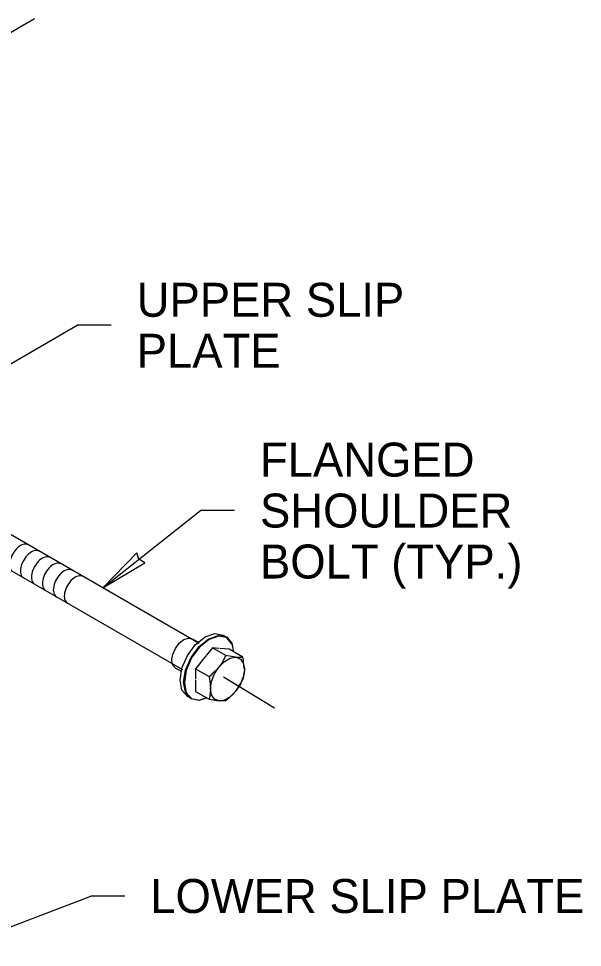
# Model space of a CAD drawing. Extents: x 99862 to 103151, y 99997 to 117076.
# Drawn here: x 101923.2 to 102188.8, y 116043.6 to 116481.1 of the extents above; entities that cross this region are included whole.
import ezdxf

# ---------------------------------------------------------------- set-up
doc = ezdxf.new("R2010")
doc.units = 0
for name, color, linetype in [('Level 13', 7, 'Continuous'), ('Level 15', 7, 'Continuous'), ('Level 20', 7, 'Continuous'), ('Level 3', 7, 'Continuous'), ('Level 5', 7, 'Continuous'), ('Level 9', 7, 'Continuous')]:
    doc.layers.add(name, color=color, linetype=linetype)

msp = doc.modelspace()

# ---------------------------------------------------------------- linework, layer by layer
at = {"layer": 'Level 13'}
for p, q in [((102008.19, 116186.76), (101917.42, 116239.17)), ((102000.5, 116174.38), (101910.13, 116226.55))]:
    msp.add_line(p, q, dxfattribs=at)
for centre, start_param, end_param in [((101924.08, 116226.91), 6.283172, 9.424785), ((101929.23, 116223.93), 6.283179, 9.424784), ((101934.39, 116220.96), 6.283177, 9.424782), ((101939.54, 116217.98), 6.283174, 9.424785), ((101944.69, 116215.01), 6.283176, 9.424783), ((101949.85, 116212.03), 6.283178, 9.42478)]:
    msp.add_ellipse(centre, major_axis=(3.64, 6.31), ratio=0.57735, start_param=start_param, end_param=end_param, dxfattribs=at)
at = {"layer": 'Level 15'}
for p, q in [((101919.42, 116474.59), (101930.71, 116481.11)), ((101894.55, 116304.14), (101950.85, 116336.64)), ((101966.85, 116336.64), (101950.85, 116336.64)), ((101962.8, 116212.96), (102008.92, 116249.37)), ((102024.92, 116249.37), (102008.92, 116249.37)), ((102043.81, 116156.23), (102019.68, 116170.94)), ((101894.22, 116043.6), (101957.22, 116067.81)), ((101973.22, 116067.81), (101957.22, 116067.81))]:
    msp.add_line(p, q, dxfattribs=at)
msp.add_lwpolyline([(101962.83, 116212.93), (101982.58, 116224.77), (101979.89, 116226.45), (101978.87, 116229.45)], close=True, dxfattribs=at)
at = {"layer": 'Level 3'}
for p, q in [((102012.94, 116188.66), (102012.94, 116188.71)), ((102017.37, 116190.22), (102017.39, 116190.28)), ((102021.13, 116189.5), (102021.16, 116189.56)), ((102023.69, 116186.65), (102021.16, 116189.56)), ((102008.5, 116185.04), (102008.48, 116185.08)), ((102023.72, 116186.91), (102024.49, 116182.84)), ((102021.28, 116180.98), (102021.18, 116180.94)), ((102004.74, 116179.93), (102004.71, 116179.95)), ((102002.23, 116174.09), (102002.19, 116174.09)), ((102001.35, 116168.43), (102001.3, 116168.4)), ((102004.44, 116160.69), (102001.88, 116163.65)), ((102004.74, 116160.9), (102004.71, 116160.84)), ((102008.5, 116160.17), (102008.48, 116160.11))]:
    msp.add_line(p, q, dxfattribs=at)
for points in [[(102008.28, 116185.32), (102012.8, 116189), (102012.8, 116189)], [(102012.95, 116188.66), (102012.94, 116188.71), (102008.48, 116185.08)], [(102012.8, 116189), (102017.32, 116190.6), (102017.32, 116190.6)], [(102017.38, 116190.22), (102017.39, 116190.28), (102012.94, 116188.71)], [(102017.32, 116190.6), (102021.16, 116189.86), (102021.16, 116189.86)], [(102021.14, 116189.49), (102021.16, 116189.56), (102017.39, 116190.28)], [(102021.16, 116189.86), (102023.72, 116186.91), (102023.72, 116186.91)], [(102004.44, 116180.1), (102008.28, 116185.32), (102008.28, 116185.31)], [(102008.51, 116185.05), (102008.48, 116185.08), (102004.71, 116179.95)], [(102023.64, 116186.59), (102023.69, 116186.65), (102024.4, 116182.89)], [(102004.75, 116179.94), (102004.71, 116179.95), (102002.19, 116174.09)], [(102002.24, 116174.11), (102002.19, 116174.09), (102001.3, 116168.4)], [(102001.02, 116168.38), (102001.01, 116168.37), (102001.01, 116168.37), (102000.98, 116168.37)], [(102001.35, 116168.44), (102001.3, 116168.4), (102002.19, 116163.75)], [(102002.19, 116163.75), (102004.71, 116160.84)], [(102008.28, 116159.95), (102004.44, 116160.69), (102004.44, 116160.69)], [(102004.74, 116160.9), (102004.71, 116160.84), (102008.48, 116160.11)], [(102011.77, 116161.19), (102008.28, 116159.95), (102008.28, 116159.95)], [(102008.49, 116160.18), (102008.48, 116160.11), (102011.68, 116161.24)]]:
    msp.add_lwpolyline(points, dxfattribs=at)
at = {"layer": 'Level 5'}
for p, q in [((102020.76, 116189.94), (102019.39, 116190.73)), ((102001.96, 116163.68), (102001.94, 116163.7))]:
    msp.add_line(p, q, dxfattribs=at)
for points in [[(101999.89, 116173.51), (101997.04, 116175.16), (101995.82, 116176.56), (101995.39, 116178.81), (101995.41, 116179.37), (101995.82, 116181.55), (101997.04, 116184.37), (101998.87, 116186.84), (102001.03, 116188.59), (102003.19, 116189.34), (102005.02, 116188.98), (102007.87, 116187.34)], [(102004.18, 116160.99), (102002.71, 116161.84), (102000.16, 116164.78), (101999.26, 116169.47), (102000.16, 116175.21), (102002.71, 116181.1), (102006.54, 116186.26), (102011.05, 116189.9), (102015.57, 116191.47), (102019.39, 116190.73)], [(102001.85, 116163.8), (102001.85, 116163.8), (102000.95, 116168.5), (102001.85, 116174.23), (102004.41, 116180.12), (102008.23, 116185.28), (102008.77, 116185.71)], [(102011.79, 116161.18), (102011.76, 116161.17), (102011.48, 116161.08)]]:
    msp.add_lwpolyline(points, dxfattribs=at)
at = {"layer": 'Level 9'}
msp.add_line((102020.87, 116181.05), (102014.5, 116184.72), dxfattribs=at)
msp.add_line((102020.87, 116181.05), (102014.5, 116184.72), dxfattribs=at)
for points in [[(102017.58, 116184.45), (102014.5, 116184.72), (102011.56, 116181.07)], [(102017.58, 116184.45), (102014.5, 116184.72), (102011.56, 116181.07)], [(102029.54, 116174.87), (102029.53, 116174.99), (102029.2, 116178.27), (102029.15, 116178.69), (102028.83, 116180.34), (102022.46, 116184.01), (102017.99, 116184.41)], [(102029.54, 116174.87), (102029.53, 116174.99), (102029.2, 116178.27), (102029.15, 116178.69), (102028.83, 116180.34), (102022.46, 116184.01), (102017.99, 116184.41)], [(102011.42, 116180.89), (102006.54, 116174.82), (102006.54, 116169.94)], [(102011.42, 116180.89), (102006.54, 116174.82), (102006.54, 116169.94)], [(102018.92, 116177.51), (102017.69, 116175.8), (102020.18, 116178.27), (102022.88, 116179.85), (102025.39, 116180.3), (102024.49, 116180.4), (102022.5, 116180.76), (102020.87, 116181.05), (102019.77, 116179.06), (102018.92, 116177.51)], [(102018.92, 116177.51), (102017.69, 116175.8), (102020.18, 116178.27), (102022.88, 116179.85), (102025.39, 116180.3), (102024.49, 116180.4), (102022.5, 116180.76), (102020.87, 116181.05), (102019.77, 116179.06), (102018.92, 116177.51)], [(102025.39, 116180.3), (102025.73, 116180.27), (102026.18, 116180.24), (102027.79, 116180.25), (102028.18, 116180.26), (102028.83, 116180.34)], [(102025.39, 116180.3), (102025.73, 116180.27), (102026.18, 116180.24), (102027.79, 116180.25), (102028.18, 116180.26), (102028.83, 116180.34)], [(102025.73, 116180.27), (102027.7, 116179.44), (102029.04, 116177.55), (102029.54, 116174.87)], [(102025.73, 116180.27), (102027.7, 116179.44), (102029.04, 116177.55), (102029.54, 116174.87)], [(102006.54, 116174.82), (102012.9, 116171.15), (102014.32, 116172.32), (102014.71, 116172.71), (102017.32, 116175.35), (102017.51, 116175.58), (102017.69, 116175.8)], [(102006.54, 116174.82), (102012.9, 116171.15), (102014.32, 116172.32), (102014.71, 116172.71), (102017.32, 116175.35), (102017.51, 116175.58), (102017.69, 116175.8)], [(102017.6, 116159.77), (102015.53, 116160.55), (102014.12, 116162.5), (102013.62, 116165.37), (102014.08, 116168.8), (102015.47, 116172.39), (102017.51, 116175.58)], [(102017.6, 116159.77), (102015.53, 116160.55), (102014.12, 116162.5), (102013.62, 116165.37), (102014.08, 116168.8), (102015.47, 116172.39), (102017.51, 116175.58)], [(102029.54, 116174.37), (102029.03, 116171.11), (102027.69, 116167.67), (102025.7, 116164.54)], [(102029.54, 116174.37), (102029.03, 116171.11), (102027.69, 116167.67), (102025.7, 116164.54)], [(102029.54, 116174.87), (102029.54, 116174.37), (102029.44, 116172.79), (102029.15, 116171.34), (102028.83, 116169.72)], [(102029.54, 116174.87), (102029.54, 116174.37), (102029.44, 116172.79), (102029.15, 116171.34), (102028.83, 116169.72)], [(102006.54, 116169.54), (102006.54, 116164.21), (102012.9, 116160.53), (102014.74, 116160.21), (102016.53, 116159.89), (102017.6, 116159.77)], [(102006.54, 116169.54), (102006.54, 116164.21), (102012.9, 116160.53), (102014.74, 116160.21), (102016.53, 116159.89), (102017.6, 116159.77)], [(102012.9, 116171.15), (102013.26, 116168.99), (102013.51, 116167.44), (102013.6, 116165.38), (102013.61, 116165.06), (102013.27, 116162.17), (102013.23, 116161.8), (102012.9, 116160.53)], [(102012.9, 116171.15), (102013.26, 116168.99), (102013.51, 116167.44), (102013.6, 116165.38), (102013.61, 116165.06), (102013.27, 116162.17), (102013.23, 116161.8), (102012.9, 116160.53)], [(102025.41, 116164.19), (102025.7, 116164.54), (102025.83, 116164.71), (102027.77, 116167.73), (102028.06, 116168.18), (102028.83, 116169.72)], [(102025.41, 116164.19), (102025.7, 116164.54), (102025.83, 116164.71), (102027.77, 116167.73), (102028.06, 116168.18), (102028.83, 116169.72)], [(102025.41, 116164.19), (102024.05, 116162.66), (102022.52, 116161.3), (102020.87, 116159.82), (102020.22, 116159.74), (102019.76, 116159.71), (102019.73, 116159.71), (102017.6, 116159.77)], [(102017.6, 116159.77), (102020.12, 116160.15), (102022.87, 116161.7), (102025.41, 116164.19)], [(102025.41, 116164.19), (102024.05, 116162.66), (102022.52, 116161.3), (102020.87, 116159.82), (102020.22, 116159.74), (102019.76, 116159.71), (102019.73, 116159.71), (102017.6, 116159.77)], [(102017.6, 116159.77), (102020.12, 116160.15), (102022.87, 116161.7), (102025.41, 116164.19)]]:
    msp.add_lwpolyline(points, dxfattribs=at)

# ---------------------------------------------------------------- texts
at = {"layer": 'Level 20'}
for s, p in [('UPPER SLIP', (101978.84, 116340.65)), ('PLATE', (101978.84, 116316.65)), ('FLANGED', (102036.91, 116265.37)), ('SHOULDER ', (102036.91, 116241.37)), ('BOLT (TYP.)', (102036.91, 116217.37)), ('LOWER SLIP PLATE', (101985.21, 116059.81))]:
    msp.add_text(s, height=16, dxfattribs=at).set_placement(p)

doc.saveas('drawing.dxf')
